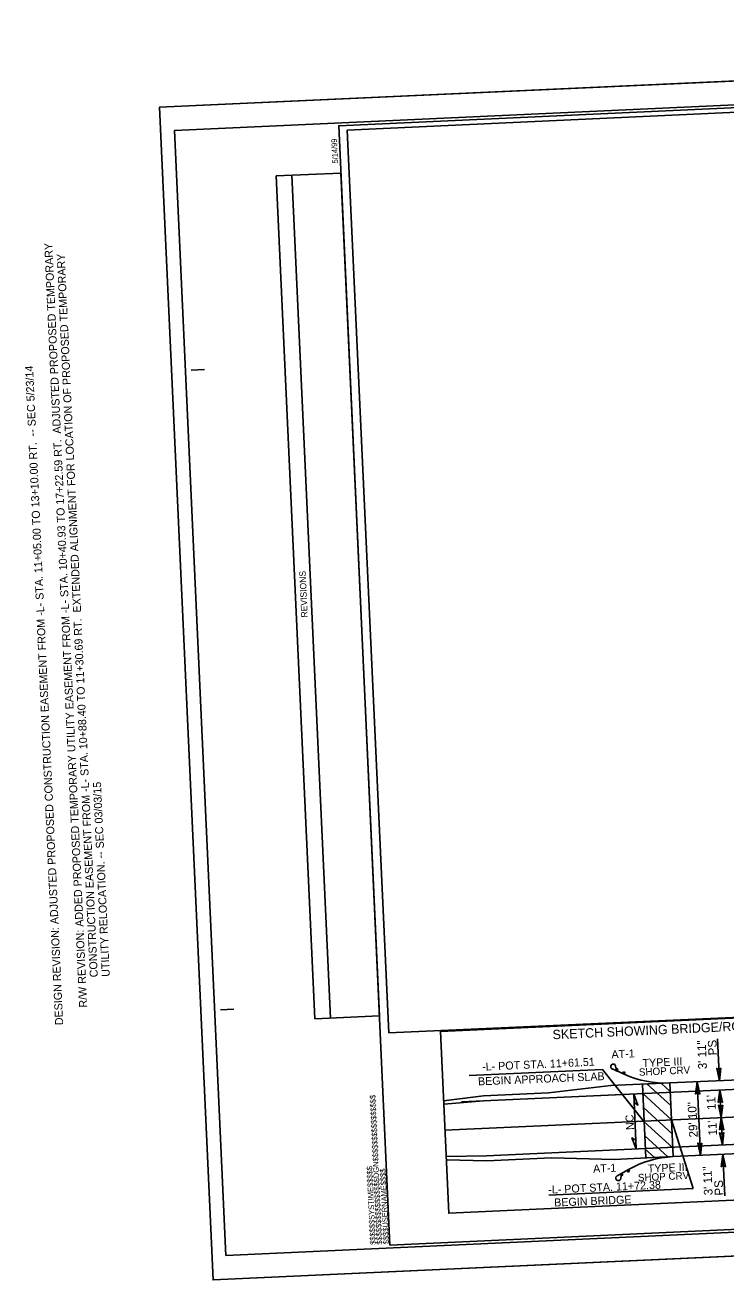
# Model space of a CAD drawing. Extents: x 1191067 to 1191874, y 892813 to 893283.
# Drawn here: x 1191066.6 to 1191329.2, y 892813.1 to 893283.5 of the extents above; entities that cross this region are included whole.
import ezdxf

# ---------------------------------------------------------------- set-up
doc = ezdxf.new("R2010")
doc.units = 0
for name, color, linetype in [('Prop Approach Slab', 7, 'Continuous'), ('Prop DSN Text', 7, 'Continuous'), ('Prop EOT', 7, 'Continuous'), ('Prop Guardrail Anchor Unit CELL', 7, 'Continuous'), ('Prop Guardrail Shop Curved', 7, 'Continuous'), ('Prop Horizontal Alignment', 7, 'Continuous'), ('Prop Leader Line Medium', 7, 'Continuous'), ('Prop Paved Shoulder', 7, 'Continuous'), ('Prop Roadway Bridge', 7, 'Continuous'), ('Prop Superelevation  Arrow CELL', 7, 'Continuous'), ('Prop Superelevation Label', 7, 'Continuous'), ('Prop Terminator CELL', 7, 'Continuous'), ('Sheet Block Revision CELL', 7, 'Continuous'), ('Sheet Border Standard 30in CELL', 7, 'Continuous'), ('Sheet Clip Boundary CELL', 7, 'Continuous'), ('Sheet Cutting Line CELL', 7, 'Continuous'), ('Sheet Plot Border Inside CELL', 7, 'Continuous'), ('Sheet Plot Border Outside CELL', 7, 'Continuous')]:
    doc.layers.add(name, color=color, linetype=linetype)

msp = doc.modelspace()

# ---------------------------------------------------------------- linework, layer by layer
at = {"layer": 'Prop Approach Slab'}
for p, q in [((1191297.92, 892886.49), (1191308.22, 892886.96)), ((1191297.92, 892886.49), (1191299.18, 892858.86)), ((1191308.61, 892878.48), (1191299.74, 892886.57)), ((1191308.37, 892883.78), (1191305.04, 892886.82)), ((1191308.85, 892873.18), (1191298.08, 892883.01)), ((1191309.09, 892867.89), (1191298.32, 892877.72)), ((1191309.34, 892862.59), (1191298.56, 892872.42)), ((1191307.44, 892859.24), (1191298.8, 892867.12)), ((1191302.5, 892859.02), (1191299.03, 892862.18)), ((1191299.18, 892858.86), (1191309.48, 892859.34))]:
    msp.add_line(p, q, dxfattribs=at)
at = {"layer": 'Prop DSN Text'}
for p, q in [((1191326.8, 892887.81), (1191326.08, 892903.53)), ((1191319.69, 892859.8), (1191318.43, 892887.43)), ((1191327.43, 892874), (1191326.96, 892884.3)), ((1191327.91, 892863.7), (1191327.43, 892874)), ((1191328.78, 892844.62), (1191328.07, 892860.19))]:
    msp.add_line(p, q, dxfattribs=at)
at = {"layer": 'Prop EOT'}
for p, q in [((1191230.16, 892879.9), (1191385.24, 892887)), ((1191238.44, 892880.25), (1191383.84, 892886.9)), ((1191238.44, 892880.25), (1191223.48, 892878.99)), ((1191239.47, 892859.65), (1191382.94, 892866.22)), ((1191239.47, 892859.65), (1191224.38, 892859.4))]:
    msp.add_line(p, q, dxfattribs=at)
at = {"layer": 'Prop Guardrail Anchor Unit CELL'}
for p, q in [((1191288.08, 892891.59), (1191286.61, 892892.25)), ((1191287.86, 892891.69), (1191288.17, 892892.38)), ((1191287.86, 892891.69), (1191288.77, 892892.11)), ((1191287.86, 892891.69), (1191287.99, 892891.99)), ((1191287.86, 892891.69), (1191287.99, 892891.99)), ((1191288.46, 892891.42), (1191287.86, 892891.69)), ((1191287.9, 892893.3), (1191288.13, 892892.29)), ((1191287.97, 892891.64), (1191288.08, 892891.59)), ((1191287.97, 892891.64), (1191288.08, 892891.59)), ((1191291.12, 892890.23), (1191288.08, 892891.59)), ((1191288.17, 892892.38), (1191288.77, 892892.11)), ((1191288.46, 892891.42), (1191288.17, 892892.38)), ((1191288.77, 892892.11), (1191288.46, 892891.42)), ((1191290.52, 892890.5), (1191290.83, 892891.19)), ((1191290.52, 892890.5), (1191291.43, 892890.92)), ((1191291.12, 892890.23), (1191290.52, 892890.5)), ((1191290.83, 892891.19), (1191291.43, 892890.92)), ((1191291.12, 892890.23), (1191290.83, 892891.19)), ((1191291.43, 892890.92), (1191291.12, 892890.23)), ((1191289.85, 892852.9), (1191288.44, 892852.11)), ((1191290.26, 892853.13), (1191289.68, 892852.81)), ((1191289.68, 892852.81), (1191289.85, 892852.52)), ((1191289.68, 892852.81), (1191289.85, 892852.52)), ((1191289.68, 892852.81), (1191290.05, 892852.15)), ((1191289.68, 892852.81), (1191290.63, 892852.47)), ((1191289.79, 892852.87), (1191289.9, 892852.93)), ((1191289.79, 892852.87), (1191289.9, 892852.93)), ((1191289.82, 892851.18), (1191289.97, 892852.3)), ((1191292.74, 892854.53), (1191289.85, 892852.9)), ((1191290.26, 892853.13), (1191290.05, 892852.15)), ((1191290.05, 892852.15), (1191290.63, 892852.47)), ((1191290.63, 892852.47), (1191290.26, 892853.13)), ((1191292.74, 892854.53), (1191292.17, 892854.21)), ((1191292.17, 892854.21), (1191292.54, 892853.55)), ((1191292.17, 892854.21), (1191293.11, 892853.87)), ((1191292.74, 892854.53), (1191292.54, 892853.55)), ((1191292.54, 892853.55), (1191293.11, 892853.87)), ((1191293.11, 892853.87), (1191292.74, 892854.53))]:
    msp.add_line(p, q, dxfattribs=at)
for centre, major_axis, start_param, end_param in [((1191286.99, 892893.09), (-0.381, -0.85), 2.210226, 6.283185), ((1191288.9, 892851.3), (0.456, -0.812), 3.141593, 7.214552)]:
    msp.add_ellipse(centre, major_axis=major_axis, ratio=0.995379, start_param=start_param, end_param=end_param, dxfattribs=at)
at = {"layer": 'Prop Guardrail Shop Curved'}
for centre, start, end in [((1191306.51, 892924.42), 245.7621, 272.6195), ((1191311.2, 892821.88), 92.6195, 119.4802)]:
    msp.add_arc(centre, 37.5, start, end, dxfattribs=at)
at = {"layer": 'Prop Horizontal Alignment'}
msp.add_line((1191223.93, 892869.26), (1191382.47, 892876.52), dxfattribs=at)
at = {"layer": 'Prop Leader Line Medium'}
for p, q in [((1191232.96, 892889.77), (1191283, 892892.06)), ((1191283, 892892.06), (1191298.56, 892872.42)), ((1191308.85, 892873.15), (1191317, 892847.37)), ((1191262.83, 892844.89), (1191317, 892847.37))]:
    msp.add_line(p, q, dxfattribs=at)
msp.add_lwpolyline([(1191222.24, 892906.26), (1191421.97, 892915.4), (1191425.09, 892847.28), (1191225.35, 892838.14)], close=True, dxfattribs=at)
at = {"layer": 'Prop Paved Shoulder'}
for p, q in [((1191286.09, 892885.95), (1191262.75, 892883.24)), ((1191286.09, 892885.95), (1191308.22, 892886.96)), ((1191238.36, 892882.12), (1191223.43, 892880.26)), ((1191238.36, 892882.12), (1191262.75, 892883.24)), ((1191239.57, 892857.78), (1191224.44, 892858.13)), ((1191239.57, 892857.78), (1191263.87, 892858.89)), ((1191287.35, 892858.32), (1191263.87, 892858.89)), ((1191287.35, 892858.32), (1191309.48, 892859.34))]:
    msp.add_line(p, q, dxfattribs=at)
at = {"layer": 'Prop Roadway Bridge'}
for p, q in [((1191308.22, 892886.96), (1191341, 892888.46)), ((1191308.22, 892886.96), (1191309.48, 892859.34)), ((1191309.48, 892859.34), (1191342.26, 892860.84))]:
    msp.add_line(p, q, dxfattribs=at)
at = {"layer": 'Prop Superelevation  Arrow CELL'}
msp.add_line((1191295.62, 892862.22), (1191294.68, 892882.82), dxfattribs=at)
for points in [[(1191294.68, 892882.82), (1191296.28, 892878.67), (1191294.83, 892879.58)], [(1191295.62, 892862.22), (1191294.02, 892866.37), (1191295.47, 892865.47)]]:
    msp.add_lwpolyline(points, close=True, dxfattribs=at)
at = {"layer": 'Prop Terminator CELL'}
for points in [[(1191327.39, 892892.46), (1191326.8, 892887.81), (1191325.77, 892892.41), (1191326.62, 892891.86)], [(1191317.84, 892882.78), (1191318.43, 892887.43), (1191319.46, 892882.83), (1191318.61, 892883.38)], [(1191326.38, 892879.65), (1191326.96, 892884.3), (1191328, 892879.7), (1191327.15, 892880.25)], [(1191328.02, 892878.65), (1191327.43, 892874), (1191326.4, 892878.6), (1191327.25, 892878.05)], [(1191326.85, 892869.35), (1191327.43, 892874), (1191328.47, 892869.4), (1191327.62, 892869.95)], [(1191328.49, 892868.35), (1191327.91, 892863.7), (1191326.87, 892868.3), (1191327.72, 892867.75)], [(1191320.27, 892864.45), (1191319.69, 892859.8), (1191318.66, 892864.4), (1191319.51, 892863.85)], [(1191327.48, 892855.54), (1191328.07, 892860.19), (1191329.1, 892855.59), (1191328.25, 892856.14)]]:
    msp.add_lwpolyline(points, close=True, dxfattribs=at)
at = {"layer": 'Sheet Block Revision CELL'}
msp.add_line((1191181, 892911.25), (1191166.54, 893227.18), dxfattribs=at)
msp.add_lwpolyline([(1191175.18, 892910.99), (1191160.73, 893226.92), (1191184.92, 893228.03), (1191199.38, 892912.1)], close=True, dxfattribs=at)
at = {"layer": 'Sheet Border Standard 30in CELL'}
for p, q in [((1191184.51, 893245.76), (1191184.51, 893245.76)), ((1191128.84, 893154.12), (1191133.84, 893154.35)), ((1191139.81, 892914.38), (1191144.8, 892914.6))]:
    msp.add_line(p, q, dxfattribs=at)
msp.add_lwpolyline([(1191783.48, 893273.17), (1191184.11, 893245.75), (1191203.31, 892826.19), (1191802.68, 892853.61)], close=True, dxfattribs=at)
at = {"layer": 'Sheet Clip Boundary CELL'}
msp.add_lwpolyline([(1191202.89, 892905.77), (1191187.26, 893244.08), (1191701.27, 893267.82), (1191704.06, 893207.36), (1191782.86, 893211), (1191795.71, 892932.92), (1191477.62, 892917.95)], close=True, dxfattribs=at)
at = {"layer": 'Sheet Cutting Line CELL'}
for p, q in [((1191789.82, 893283.47), (1191116.92, 893252.68)), ((1191116.92, 893252.68), (1191137.03, 892813.14)), ((1191137.03, 892813.14), (1191809.93, 892843.93))]:
    msp.add_line(p, q, dxfattribs=at)
at = {"layer": 'Sheet Plot Border Inside CELL'}
msp.add_lwpolyline([(1191788.43, 893274.42), (1191122.53, 893243.95), (1191141.82, 892822.35), (1191807.72, 892852.82)], close=True, dxfattribs=at)
at = {"layer": 'Sheet Plot Border Outside CELL'}
msp.add_lwpolyline([(1191789.82, 893283.47), (1191116.92, 893252.68), (1191137.03, 892813.14), (1191809.93, 892843.93)], close=True, dxfattribs=at)

# ---------------------------------------------------------------- texts
at = {"layer": 'Prop DSN Text'}
for s, height, rotation, p in [('R/W REVISION: ADDED PROPOSED TEMPORARY UTILITY EASEMENT FROM -L- STA. 10+40.93 TO 17+22.59 RT.  ADJUSTED PROPOSED TEMPORARY ', 3, 92.6195, (1191089.86, 892915.29)), ('          CONSTRUCTION EASEMENT FROM -L- STA. 10+88.40 TO 11+30.69 RT.  EXTENDED ALIGNMENT FOR LOCATION OF PROPOSED TEMPORARY ', 3, 92.6195, (1191094.35, 892915.49)), ('DESIGN REVISION: ADJUSTED PROPOSED CONSTRUCTION EASEMENT FROM -L- STA. 11+05.00 TO 13+10.00 RT.  -- SEC 5/23/14', 3, 92.6195, (1191080.86, 892908.69)), ('          UTILITY RELOCATION. -- SEC 03/03/15', 3, 92.6195, (1191098.85, 892915.7)), ('SKETCH SHOWING BRIDGE/ROADWAY RELATIONSHIP', 3.5, 2.6195, (1191264.34, 892903.34)), ('3\' 11"', 3.25, 92.4915, (1191322.12, 892892.18)), ('PS', 3.25, 92.4915, (1191325.93, 892897.37)), ("11'", 3.25, 92.4915, (1191325.47, 892876.92)), ('29\' 10"', 3.25, 92.4915, (1191318.68, 892866.62)), ("11'", 3.25, 92.4915, (1191325.9, 892867.34)), ('3\' 11"', 3.25, 92.4915, (1191324.28, 892844.93)), ('PS', 3.25, 92.4915, (1191328.33, 892844.83))]:
    msp.add_text(s, height=height, rotation=rotation, dxfattribs=at).set_placement(p)
at = {"layer": 'Prop Guardrail Anchor Unit CELL'}
for s, height, p in [('AT-1', 3, (1191286.41, 892896.17)), ('TYPE III', 3, (1191298.05, 892892.91)), ('SHOP CRV', 2.75, (1191296.69, 892889.64)), ('AT-1', 3, (1191279.53, 892853.31)), ('TYPE III', 3, (1191300.01, 892853.35)), ('SHOP CRV', 2.75, (1191296.32, 892850.09))]:
    msp.add_text(s, height=height, rotation=2.6195, dxfattribs=at).set_placement(p)
at = {"layer": 'Prop Leader Line Medium'}
for s, rotation, p in [('-L- POT STA. 11+61.51', 2.5888, (1191237.93, 892891.54)), ('BEGIN APPROACH SLAB', 2.4356, (1191236.38, 892886.03)), ('-L- POT STA. 11+72.38', 2.5888, (1191262.71, 892845.45)), ('BEGIN BRIDGE', 2.4356, (1191264.94, 892840.63))]:
    msp.add_text(s, height=3, rotation=rotation, dxfattribs=at).set_placement(p)
at = {"layer": 'Prop Superelevation Label'}
msp.add_text('NC', height=3, rotation=92.6195, dxfattribs=at).set_placement((1191294.83, 892869.39))
at = {"layer": 'Sheet Block Revision CELL'}
msp.add_text('REVISIONS', height=2.4, rotation=92.6195, dxfattribs=at).set_placement((1191172.5, 893061.48))
at = {"layer": 'Sheet Border Standard 30in CELL'}
for s, p in [('5/14/99', (1191183.86, 893231.64)), ('$$$$$$$$$$$$$$$$DGN$$$$$$$$$$$$$$$$', (1191200.43, 892826.39)), ('$$$$$$SYSTIME$$$$$', (1191198.01, 892826.36)), ('$$$$USERNAME$$$$', (1191202.95, 892826.55))]:
    msp.add_text(s, height=2.1, rotation=92.6195, dxfattribs=at).set_placement(p)

doc.saveas('drawing.dxf')
